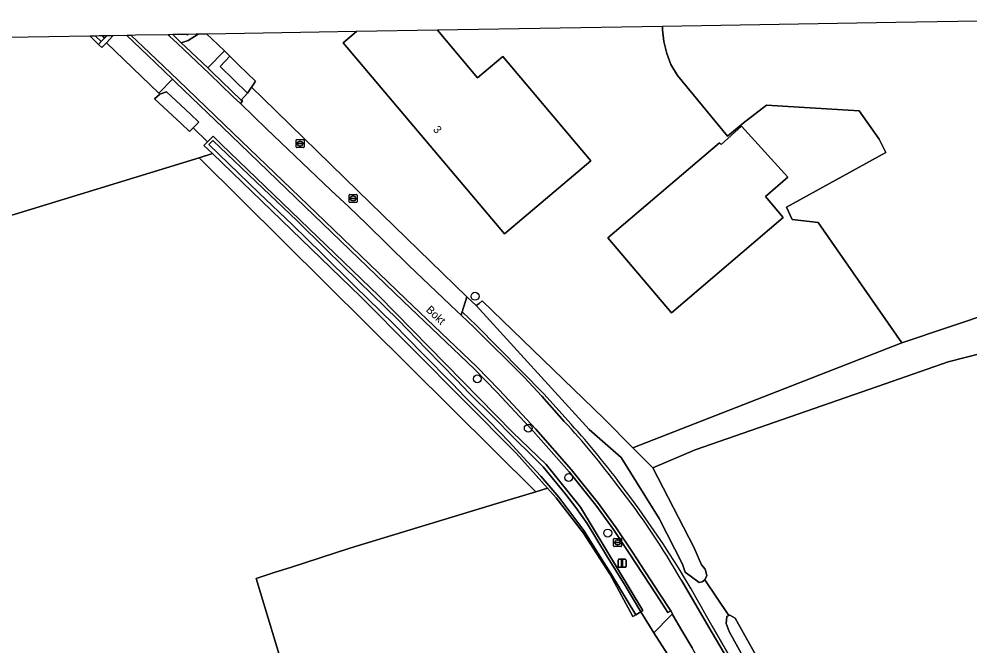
# Model space of a CAD drawing. Extents: x 162510 to 163918, y 388494 to 389774.
# Drawn here: x 163019.4 to 163138.2, y 389687.4 to 389765.6 of the extents above; entities that cross this region are included whole.
import ezdxf

# ---------------------------------------------------------------- set-up
doc = ezdxf.new("R2010")
doc.units = 0
for name, color, linetype in [('IMGEO_Afsluitpaal', 7, 'Continuous'), ('IMGEO_Berm_groen', 7, 'Continuous'), ('IMGEO_Boom', 7, 'Continuous'), ('IMGEO_Brandkraan', 7, 'Continuous'), ('IMGEO_Erf', 7, 'Continuous'), ('IMGEO_Grasland_agrarisch', 7, 'Continuous'), ('IMGEO_Grasland_overig', 7, 'Continuous'), ('IMGEO_Hek', 7, 'Continuous'), ('IMGEO_Inrit_halfverhard', 7, 'Continuous'), ('IMGEO_Kolk', 7, 'Continuous'), ('IMGEO_Loofbos', 7, 'Continuous'), ('IMGEO_Oever', 7, 'Continuous'), ('IMGEO_Openbare_ruimte_label', 7, 'Continuous'), ('IMGEO_Pand', 7, 'Continuous'), ('IMGEO_Pand_nummerreeks', 7, 'Continuous'), ('IMGEO_Rijbaan_lokaal_gesloten', 7, 'Continuous'), ('IMGEO_Rijbaan_lokaal_halfverhard', 7, 'Continuous'), ('IMGEO_Rijbaan_lokaal_open', 7, 'Continuous'), ('IMGEO_Rioolput', 7, 'Continuous'), ('IMGEO_Sloot', 7, 'Continuous'), ('IMGEO_Voetpad_open', 7, 'Continuous'), ('IMGEO_Waterloop', 7, 'Continuous')]:
    doc.layers.add(name, color=color, linetype=linetype)

msp = doc.modelspace()

# ---------------------------------------------------------------- linework, layer by layer
at = {"layer": 'IMGEO_Afsluitpaal'}
for p, q in [((163094.27, 389697.27), (163094.27, 389698.07)), ((163094.27, 389698.07), (163094.27, 389697.27)), ((163094.37, 389698.17), (163095.16, 389698.17)), ((163095.16, 389698.17), (163094.37, 389698.17)), ((163095.26, 389698.07), (163095.26, 389697.27)), ((163095.26, 389697.27), (163095.26, 389698.07)), ((163095.16, 389697.17), (163094.37, 389697.17)), ((163094.37, 389697.17), (163095.16, 389697.17))]:
    msp.add_line(p, q, dxfattribs=at)
msp.add_lwpolyline([(163094.69, 389698.04), (163094.84, 389698.04), (163094.84, 389697.29), (163094.69, 389697.29), (163094.69, 389698.04)], dxfattribs=at)
for centre, start, end in [((163094.37, 389698.07), 90, 180), ((163094.37, 389698.07), 90, 180), ((163095.16, 389698.07), 0, 90), ((163095.16, 389698.07), 360, 90), ((163094.37, 389697.27), 180, 270), ((163094.37, 389697.27), 180, 270), ((163095.16, 389697.27), 270, 0), ((163095.16, 389697.27), 270, 0)]:
    msp.add_arc(centre, 0.1, start, end, dxfattribs=at)
at = {"layer": 'IMGEO_Berm_groen'}
msp.add_lwpolyline([(163031.18, 389763.52), (163030.89, 389763.52), (163030.41, 389763.51), (163030.14, 389763.23), (163029.72, 389762.79), (163029.38, 389762.44), (163029.78, 389762.04), (163030.36, 389762.63), (163031.18, 389763.52)], dxfattribs=at)
for points in [[(163040.4, 389763.68), (163038.68, 389763.65), (163038.65, 389763.65), (163039.7, 389762.65), (163040.57, 389762.92), (163041.83, 389763.7), (163041.55, 389763.7), (163040.59, 389763.68), (163040.5, 389763.58)], [(163044.55, 389759.66), (163045.78, 389760.95), (163045.09, 389761.62), (163043.02, 389759.5), (163043.52, 389759.03), (163047.21, 389755.48), (163047.98, 389756.33)]]:
    msp.add_lwpolyline(points, close=True, dxfattribs=at)
at = {"layer": 'IMGEO_Boom'}
for centre in [(163076.41, 389731), (163076.69, 389720.69), (163083.05, 389714.53), (163088.09, 389708.37), (163092.98, 389701.44)]:
    msp.add_circle(centre, 0.489, dxfattribs=at)
at = {"layer": 'IMGEO_Brandkraan'}
for p, q in [((163093.71, 389699.84), (163093.71, 389700.7)), ((163093.78, 389700.77), (163094.64, 389700.77)), ((163093.97, 389700.26), (163093.97, 389700.28)), ((163094.01, 389700.31), (163094.41, 389700.31)), ((163094.41, 389700.23), (163094.01, 389700.23)), ((163094.2, 389700.55), (163094.22, 389700.55)), ((163094.45, 389700.28), (163094.45, 389700.26)), ((163094.71, 389700.7), (163094.71, 389699.84)), ((163094.64, 389699.77), (163093.78, 389699.77)), ((163094.22, 389699.99), (163094.2, 389699.99))]:
    msp.add_line(p, q, dxfattribs=at)
for points in [[(163093.71, 389699.84), (163093.71, 389700.7)], [(163093.78, 389700.77), (163094.64, 389700.77)], [(163094.71, 389700.7), (163094.71, 389699.84)], [(163094.64, 389699.77), (163093.78, 389699.77)]]:
    msp.add_lwpolyline(points, dxfattribs=at)
for centre, radius, start, end in [((163093.79, 389700.69), 0.0765, 91.552, 178.448), ((163093.79, 389700.69), 0.0765, 91.552, 178.448), ((163094.01, 389700.27), 0.0403, 85.8775, 175.7526), ((163094.01, 389700.26), 0.0366, 178.938, 274.7102), ((163094.41, 389700.27), 0.0386, 1.7309, 96.639), ((163094.41, 389700.27), 0.043, 264.8664, 352.4533), ((163094.63, 389700.69), 0.0765, 1.552, 88.448), ((163094.63, 389700.69), 0.0765, 1.552, 88.448), ((163093.79, 389699.84), 0.0765, 181.552, 268.448), ((163093.79, 389699.84), 0.0765, 181.552, 268.448), ((163094.63, 389699.84), 0.0765, 271.552, 358.448), ((163094.63, 389699.84), 0.0765, 271.552, 358.448)]:
    msp.add_arc(centre, radius, start, end, dxfattribs=at)
for centre, major_axis, ratio, start_param, end_param in [((163094.2, 389700.27), (-0.387, 0.002), 0.722429, 4.712389, 7.853982), ((163094.22, 389700.27), (-0.39, 0.002), 0.717154, 1.570796, 4.712389)]:
    msp.add_ellipse(centre, major_axis=major_axis, ratio=ratio, start_param=start_param, end_param=end_param, dxfattribs=at)
at = {"layer": 'IMGEO_Erf'}
for points in [[(163061.6, 389764.03), (163042.93, 389763.72), (163042.91, 389763.72), (163043.53, 389763.13), (163045.09, 389761.62), (163045.78, 389760.95), (163046.92, 389759.84), (163048.98, 389757.85), (163048.59, 389757.26), (163048.47, 389757.09), (163049.91, 389755.71), (163061.77, 389744.16), (163075.36, 389730.92), (163076.55, 389729.85), (163076.91, 389730.11), (163077.31, 389730.41), (163092.48, 389715.73), (163096.12, 389712.1), (163129.7, 389725.19), (163119.24, 389740.19), (163116.01, 389740.57), (163115.29, 389742.12), (163127.73, 389748.96), (163126.86, 389750.62), (163124.39, 389754.15), (163112.8, 389754.86), (163109.9, 389752.61), (163107.92, 389750.97), (163101.7, 389758.54), (163100.86, 389759.93), (163100.34, 389761.29), (163099.99, 389762.8), (163099.8, 389764.24), (163099.82, 389764.68), (163071.7, 389764.2), (163076.73, 389758.25), (163079.88, 389760.91), (163090.88, 389747.9), (163080.1, 389738.79), (163059.94, 389762.63)], [(163106.94, 389750.15), (163107.14, 389749.92), (163109.68, 389752.23), (163115.47, 389745.85), (163112.67, 389743.44), (163114.9, 389740.84), (163100.93, 389728.94), (163093, 389738.3)]]:
    msp.add_lwpolyline(points, close=True, dxfattribs=at)
for points in [[(163000, 389735.45), (163041.93, 389748.28), (163043.62, 389748.8), (163042.54, 389749.83), (163042.99, 389750.29), (163041.21, 389752.03), (163040.72, 389751.57), (163039.7, 389752.55), (163036.36, 389755.62), (163036.97, 389756.17), (163037.03, 389756.22), (163036.89, 389756.36), (163030.36, 389762.63), (163029.78, 389762.04), (163029.38, 389762.44), (163028.34, 389763.47), (163028.29, 389763.47), (163000, 389763)], [(163101.17, 389685.17), (163098.73, 389688.98), (163097.11, 389691.63), (163096.48, 389691.25), (163096.13, 389691.04), (163093.29, 389696.28), (163089.93, 389701.45), (163086.53, 389705.83), (163085.44, 389707.04), (163083.99, 389706.6), (163079.14, 389705.13), (163060.78, 389699.57), (163053.35, 389697.16), (163051.31, 389696.5), (163050.19, 389696.14), (163049.05, 389695.77), (163063.36, 389648.6)]]:
    msp.add_lwpolyline(points, dxfattribs=at)
at = {"layer": 'IMGEO_Grasland_agrarisch'}
msp.add_lwpolyline([(163130.74, 389593.91), (163130.82, 389595.75), (163129.49, 389604.01), (163127.31, 389615.89), (163124.17, 389630.54), (163122.35, 389637.11), (163120.08, 389643.72), (163118.81, 389646.87), (163066.29, 389636.03), (163063.36, 389648.6), (163049.05, 389695.77), (163050.19, 389696.14), (163051.31, 389696.5), (163053.35, 389697.16), (163060.78, 389699.57), (163079.14, 389705.13), (163083.99, 389706.6), (163041.93, 389748.28), (163000, 389735.45)], dxfattribs=at)
at = {"layer": 'IMGEO_Grasland_overig'}
for points in [[(163154.74, 389765.6), (163128.98, 389765.17), (163099.82, 389764.68), (163099.8, 389764.24), (163099.99, 389762.8), (163100.34, 389761.29), (163100.86, 389759.93), (163101.7, 389758.54), (163107.92, 389750.97), (163109.9, 389752.61), (163112.8, 389754.86), (163124.39, 389754.15), (163126.86, 389750.62), (163127.73, 389748.96), (163115.29, 389742.12), (163116.01, 389740.57), (163119.24, 389740.19), (163129.7, 389725.19), (163141.35, 389729.09), (163168.42, 389737.11), (163201.99, 389747.04)], [(163095.83, 389708.99), (163094.66, 389710.87), (163090.67, 389714.38), (163076.55, 389729.85), (163075.36, 389730.92), (163074.78, 389729.06), (163076.53, 389727.41), (163085.04, 389718.79), (163087.98, 389715.5)], [(163113.58, 389679.31), (163108.13, 389689.14), (163107.76, 389690.16), (163107.87, 389691.02), (163108.1, 389691.14), (163105.09, 389695.61), (163104.76, 389695.34), (163104.38, 389695.26), (163102.66, 389696.57), (163102.32, 389697.57), (163099.41, 389703.24), (163095.83, 389708.99)], [(163105.96, 389689.9), (163109.12, 389684.51), (163111.32, 389680.67), (163113.47, 389676.83), (163115.49, 389672.95), (163116.92, 389670.18), (163121.49, 389660.72)]]:
    msp.add_lwpolyline(points, dxfattribs=at)
for points in [[(163038.6, 389758.11), (163036.89, 389756.36), (163037.03, 389756.22), (163037.87, 389756.52), (163040.87, 389753.73), (163041.92, 389752.71), (163041.21, 389752.03), (163042.99, 389750.29), (163043.68, 389750.98), (163044.68, 389750), (163064.38, 389731.06), (163081.07, 389714.04), (163085.27, 389709.98), (163089.56, 389704.66), (163097.34, 389691.77), (163097.11, 389691.63), (163098.73, 389688.98), (163100.83, 389691.13), (163101.05, 389691.35), (163100.84, 389691.74), (163100.5, 389691.52), (163099.05, 389693.74), (163095.64, 389698.95), (163093.69, 389701.88), (163091.51, 389704.92), (163088.14, 389709.08), (163083.7, 389714.12), (163079.11, 389719.02), (163076.34, 389721.88), (163067.43, 389730.4), (163056.26, 389741.13), (163045.93, 389751.08), (163039.04, 389757.69)], [(163062.1, 389730.98), (163043.62, 389748.8), (163041.93, 389748.28), (163083.99, 389706.6), (163085.44, 389707.04), (163081.53, 389711.41)]]:
    msp.add_lwpolyline(points, close=True, dxfattribs=at)
for centre, radius, start, end in [((163016.59, 389649.58), 97.17, 36.6639, 42.7185), ((162991.94, 389628.88), 129.32, 28.1533, 37.4998)]:
    msp.add_arc(centre, radius, start, end, dxfattribs=at)
at = {"layer": 'IMGEO_Hek'}
for points in [[(162950.22, 389720.21), (163000, 389735.45), (163041.93, 389748.28), (163043.62, 389748.8)], [(163050.19, 389696.14), (163051.31, 389696.5), (163053.35, 389697.16), (163060.78, 389699.57), (163079.14, 389705.13), (163083.99, 389706.6), (163085.44, 389707.04)]]:
    msp.add_lwpolyline(points, dxfattribs=at)
at = {"layer": 'IMGEO_Inrit_halfverhard'}
msp.add_lwpolyline([(163041.83, 389763.7), (163040.57, 389762.92), (163039.7, 389762.65), (163040.3, 389762.09), (163043.02, 389759.5), (163045.09, 389761.62), (163043.53, 389763.13), (163042.91, 389763.72)], close=True, dxfattribs=at)
at = {"layer": 'IMGEO_Kolk'}
for p, q in [((163054.05, 389749.63), (163054.05, 389750.48)), ((163054.12, 389750.55), (163054.97, 389750.55)), ((163054.3, 389750.05), (163054.3, 389750.06)), ((163054.35, 389750.1), (163054.75, 389750.1)), ((163054.53, 389750.33), (163054.56, 389750.33)), ((163054.79, 389750.06), (163054.79, 389750.05)), ((163055.05, 389750.48), (163055.05, 389749.63)), ((163054.97, 389749.55), (163054.12, 389749.55)), ((163054.74, 389750.01), (163054.34, 389750.01)), ((163054.56, 389749.77), (163054.53, 389749.77))]:
    msp.add_line(p, q, dxfattribs=at)
for points in [[(163054.05, 389749.63), (163054.05, 389750.48)], [(163054.12, 389750.55), (163054.97, 389750.55)], [(163055.05, 389750.48), (163055.05, 389749.63)], [(163054.97, 389749.55), (163054.12, 389749.55)]]:
    msp.add_lwpolyline(points, dxfattribs=at)
for centre, radius, start, end in [((163054.12, 389750.48), 0.0765, 91.552, 178.448), ((163054.12, 389750.48), 0.0765, 91.552, 178.448), ((163054.35, 389750.06), 0.0403, 85.8775, 175.7526), ((163054.34, 389750.05), 0.0366, 178.938, 274.7102), ((163054.75, 389750.05), 0.043, 264.8664, 352.4533), ((163054.75, 389750.06), 0.0386, 1.7309, 96.639), ((163054.97, 389750.48), 0.0765, 1.552, 88.448), ((163054.97, 389750.48), 0.0765, 1.552, 88.448), ((163054.12, 389749.63), 0.0765, 181.552, 268.448), ((163054.12, 389749.63), 0.0765, 181.552, 268.448), ((163054.97, 389749.63), 0.0765, 271.552, 358.448), ((163054.97, 389749.63), 0.0765, 271.552, 358.448)]:
    msp.add_arc(centre, radius, start, end, dxfattribs=at)
for centre, major_axis, ratio, start_param, end_param in [((163054.53, 389750.05), (-0.387, 0.002), 0.722429, 4.712389, 7.853982), ((163054.56, 389750.05), (-0.39, 0.002), 0.717154, 1.570796, 4.712389)]:
    msp.add_ellipse(centre, major_axis=major_axis, ratio=ratio, start_param=start_param, end_param=end_param, dxfattribs=at)
at = {"layer": 'IMGEO_Loofbos'}
msp.add_lwpolyline([(163146.11, 389725.52), (163135.48, 389722.83), (163127.61, 389720.05), (163103.91, 389711.81), (163098.61, 389709.59), (163103.73, 389699.69), (163104.68, 389697.49), (163105.15, 389696.93), (163105.37, 389696.14), (163105.09, 389695.61), (163108.1, 389691.14), (163108.23, 389691.19), (163108.91, 389690.83), (163115.83, 389678.38), (163116.72, 389677.86), (163117.45, 389677.93), (163121.25, 389679.04), (163131.11, 389682.28), (163161.64, 389691.33)], dxfattribs=at)
at = {"layer": 'IMGEO_Oever'}
for points in [[(163029, 389763.48), (163028.34, 389763.47), (163029.38, 389762.44), (163029.72, 389762.79)], [(163030.41, 389763.51), (163029.88, 389763.5), (163030.14, 389763.23)], [(163043.15, 389749.92), (163043.67, 389750.46), (163049.92, 389744.43), (163054.13, 389740.45), (163057.78, 389736.87), (163061.87, 389732.84), (163066.8, 389728.05), (163070.34, 389724.4), (163074.1, 389720.57), (163075.64, 389718.96), (163078.77, 389715.85), (163081.19, 389713.38), (163083.59, 389711.03), (163084.93, 389709.69), (163087.73, 389706.24), (163088.99, 389704.63), (163090.4, 389702.64), (163092.83, 389698.63), (163095.14, 389694.9), (163097.11, 389691.63), (163097.34, 389691.77), (163089.56, 389704.66), (163085.27, 389709.98), (163081.07, 389714.04), (163064.38, 389731.06), (163044.68, 389750), (163043.68, 389750.98), (163042.99, 389750.29), (163042.54, 389749.83), (163043.62, 389748.8), (163062.1, 389730.98), (163081.53, 389711.41), (163085.44, 389707.04), (163086.53, 389705.83), (163089.93, 389701.45), (163093.29, 389696.28), (163096.13, 389691.04), (163096.48, 389691.25), (163093.38, 389696.4), (163092.19, 389698.24), (163090, 389701.76), (163088.26, 389704.08), (163086.86, 389705.93), (163084.64, 389708.56), (163082.93, 389710.39), (163080.66, 389712.85), (163078.24, 389715.33), (163075.11, 389718.44), (163073.57, 389720.05), (163069.81, 389723.88), (163066.28, 389727.53), (163061.35, 389732.31), (163057.26, 389736.34), (163053.62, 389739.92), (163049.41, 389743.89)]]:
    msp.add_lwpolyline(points, close=True, dxfattribs=at)
at = {"layer": 'IMGEO_Pand'}
for points in [[(163061.6, 389764.03), (163059.94, 389762.63), (163080.1, 389738.79), (163090.88, 389747.9), (163079.88, 389760.91), (163076.73, 389758.25), (163071.7, 389764.2)], [(163114.9, 389740.84), (163112.67, 389743.44), (163115.47, 389745.85), (163109.68, 389752.23), (163107.14, 389749.92), (163106.94, 389750.15), (163093, 389738.3), (163100.93, 389728.94)]]:
    msp.add_lwpolyline(points, close=True, dxfattribs=at)
at = {"layer": 'IMGEO_Rijbaan_lokaal_gesloten'}
for points in [[(163087.55, 389715.37), (163084.74, 389718.53), (163082.54, 389720.88), (163076.25, 389727.13), (163074.65, 389728.64), (163074.12, 389729.14), (163068.12, 389734.84), (163062.86, 389740.02), (163060.62, 389742.15), (163058.38, 389744.23), (163050.35, 389751.88), (163047.09, 389755.05), (163046.17, 389755.93), (163043.25, 389758.74), (163040.02, 389761.8), (163039.24, 389762.55), (163038.25, 389763.47), (163038.07, 389763.64), (163034.01, 389763.57), (163033.47, 389763.56)], [(163033.47, 389763.56), (163035.76, 389761.38), (163039.32, 389757.98), (163046.2, 389751.36), (163056.54, 389741.42), (163067.71, 389730.69), (163076.61, 389722.17), (163079.4, 389719.3), (163083.99, 389714.39), (163088.44, 389709.34), (163091.83, 389705.15), (163094.02, 389702.1), (163095.98, 389699.17), (163099.39, 389693.96), (163100.84, 389691.74), (163101.05, 389691.35), (163101.12, 389691.21), (163102.25, 389689.27), (163103.52, 389687.12)], [(163121.13, 389660.55), (163119.32, 389664.34), (163116.56, 389670), (163115.13, 389672.76), (163113.12, 389676.63), (163110.97, 389680.47), (163108.78, 389684.31), (163105.61, 389689.69), (163102.22, 389695.47)]]:
    msp.add_lwpolyline(points, dxfattribs=at)
for centre, radius, start, end in [((163016.69, 389649.66), 96.64, 36.6551, 42.8406), ((163016.2, 389646.21), 99.13, 29.7944, 38.0848)]:
    msp.add_arc(centre, radius, start, end, dxfattribs=at)
at = {"layer": 'IMGEO_Rijbaan_lokaal_halfverhard'}
for points in [[(163033.47, 389763.56), (163032.99, 389763.55), (163032.9, 389763.55), (163035.48, 389761.09), (163038.6, 389758.11), (163039.04, 389757.69), (163045.93, 389751.08), (163056.26, 389741.13), (163067.43, 389730.4), (163076.34, 389721.88), (163079.11, 389719.02), (163083.7, 389714.12), (163088.14, 389709.08), (163091.51, 389704.92), (163093.69, 389701.88), (163095.64, 389698.95), (163099.05, 389693.74), (163100.5, 389691.52), (163100.84, 389691.74), (163099.39, 389693.96), (163095.98, 389699.17), (163094.02, 389702.1), (163091.83, 389705.15), (163088.44, 389709.34), (163083.99, 389714.39), (163079.4, 389719.3), (163076.61, 389722.17), (163067.71, 389730.69), (163056.54, 389741.42), (163046.2, 389751.36), (163039.32, 389757.98), (163035.76, 389761.38)], [(163038.07, 389763.64), (163038.25, 389763.47), (163039.24, 389762.55), (163040.02, 389761.8), (163043.25, 389758.74), (163046.17, 389755.93), (163047.09, 389755.05), (163047.36, 389755.34), (163047.21, 389755.48), (163043.52, 389759.03), (163043.02, 389759.5), (163040.3, 389762.09), (163039.7, 389762.65), (163038.65, 389763.65), (163038.3, 389763.64)]]:
    msp.add_lwpolyline(points, close=True, dxfattribs=at)
for points in [[(163074.78, 389729.06), (163074.65, 389728.64), (163076.25, 389727.13), (163082.54, 389720.88), (163084.74, 389718.53), (163087.55, 389715.37)], [(163087.98, 389715.5), (163085.04, 389718.79), (163076.53, 389727.41), (163074.78, 389729.06)], [(163102.22, 389695.47), (163105.61, 389689.69), (163108.78, 389684.31), (163110.97, 389680.47), (163113.12, 389676.63), (163115.13, 389672.76), (163116.56, 389670), (163119.32, 389664.34), (163121.13, 389660.55)], [(163121.49, 389660.72), (163116.92, 389670.18), (163115.49, 389672.95), (163113.47, 389676.83), (163111.32, 389680.67), (163109.12, 389684.51), (163105.96, 389689.9)]]:
    msp.add_lwpolyline(points, dxfattribs=at)
for centre, radius, start, end in [((163016.69, 389649.66), 96.64, 36.6551, 42.8406), ((163016.59, 389649.58), 97.17, 36.6639, 42.7185), ((163016.2, 389646.21), 99.13, 29.7944, 38.0848), ((162991.94, 389628.88), 129.32, 28.1533, 37.4998)]:
    msp.add_arc(centre, radius, start, end, dxfattribs=at)
at = {"layer": 'IMGEO_Rijbaan_lokaal_open'}
for points in [[(163032.9, 389763.55), (163031.18, 389763.52), (163030.36, 389762.63), (163036.89, 389756.36), (163038.6, 389758.11), (163035.48, 389761.09)], [(163101.05, 389691.35), (163100.83, 389691.13), (163098.73, 389688.98), (163101.17, 389685.17), (163101.39, 389685.23), (163103.88, 389685.65), (163104.31, 389685.72), (163104.28, 389685.76), (163103.52, 389687.12), (163102.25, 389689.27), (163101.12, 389691.21)]]:
    msp.add_lwpolyline(points, close=True, dxfattribs=at)
at = {"layer": 'IMGEO_Rioolput'}
for p, q in [((163060.66, 389742.78), (163060.66, 389743.63)), ((163060.74, 389743.71), (163061.59, 389743.71)), ((163060.92, 389743.2), (163060.92, 389743.21)), ((163061.36, 389743.16), (163060.96, 389743.16)), ((163060.97, 389743.25), (163061.36, 389743.25)), ((163061.15, 389743.49), (163061.18, 389743.49)), ((163061.17, 389742.93), (163061.15, 389742.93)), ((163061.41, 389743.21), (163061.41, 389743.2)), ((163061.67, 389743.63), (163061.67, 389742.78)), ((163061.59, 389742.71), (163060.74, 389742.71))]:
    msp.add_line(p, q, dxfattribs=at)
for points in [[(163060.66, 389742.78), (163060.66, 389743.63)], [(163060.74, 389743.71), (163061.59, 389743.71)], [(163061.67, 389743.63), (163061.67, 389742.78)], [(163061.59, 389742.71), (163060.74, 389742.71)]]:
    msp.add_lwpolyline(points, dxfattribs=at)
for centre, radius, start, end in [((163060.74, 389743.63), 0.0765, 91.552, 178.448), ((163060.74, 389743.63), 0.0765, 91.552, 178.448), ((163060.96, 389743.21), 0.0403, 85.8775, 175.7526), ((163060.96, 389743.2), 0.0366, 178.938, 274.7102), ((163061.37, 389743.21), 0.0386, 1.7309, 96.639), ((163061.36, 389743.21), 0.043, 264.8664, 352.4533), ((163061.59, 389743.63), 0.0765, 1.552, 88.448), ((163061.59, 389743.63), 0.0765, 1.552, 88.448), ((163060.74, 389742.78), 0.0765, 181.552, 268.448), ((163060.74, 389742.78), 0.0765, 181.552, 268.448), ((163061.59, 389742.78), 0.0765, 271.552, 358.448), ((163061.59, 389742.78), 0.0765, 271.552, 358.448)]:
    msp.add_arc(centre, radius, start, end, dxfattribs=at)
for centre, major_axis, ratio, start_param, end_param in [((163061.15, 389743.21), (-0.387, 0.002), 0.722429, 4.712389, 7.853982), ((163061.18, 389743.21), (-0.39, 0.002), 0.717154, 1.570796, 4.712389)]:
    msp.add_ellipse(centre, major_axis=major_axis, ratio=ratio, start_param=start_param, end_param=end_param, dxfattribs=at)
at = {"layer": 'IMGEO_Sloot'}
for points in [[(163029.88, 389763.5), (163029.46, 389763.49), (163029, 389763.48), (163029.72, 389762.79), (163030.14, 389763.23)], [(163040.59, 389763.68), (163040.43, 389763.68), (163040.4, 389763.68), (163040.5, 389763.58)], [(163046.92, 389759.84), (163045.78, 389760.95), (163044.55, 389759.66), (163047.98, 389756.33), (163048.47, 389757.09), (163048.59, 389757.26), (163048.98, 389757.85)], [(163037.03, 389756.22), (163036.97, 389756.17), (163036.36, 389755.62), (163039.7, 389752.55), (163040.72, 389751.57), (163041.21, 389752.03), (163041.92, 389752.71), (163040.87, 389753.73), (163037.87, 389756.52)]]:
    msp.add_lwpolyline(points, close=True, dxfattribs=at)
for points in [[(163201.99, 389747.04), (163168.42, 389737.11), (163141.35, 389729.09), (163129.7, 389725.19), (163096.12, 389712.1), (163098.61, 389709.59), (163103.91, 389711.81), (163127.61, 389720.05), (163135.48, 389722.83), (163146.11, 389725.52), (163158.42, 389728.94), (163175.95, 389733.92), (163192.61, 389739.52), (163206.42, 389743.82)], [(163161.64, 389691.33), (163131.11, 389682.28), (163121.25, 389679.04), (163117.45, 389677.93), (163116.72, 389677.86), (163115.83, 389678.38), (163108.91, 389690.83), (163108.23, 389691.19), (163108.1, 389691.14), (163107.87, 389691.02), (163107.76, 389690.16), (163108.13, 389689.14), (163113.58, 389679.31), (163122.8, 389662.04), (163123.23, 389661.71), (163123.61, 389661.72), (163124.04, 389662.03), (163123.95, 389662.66), (163122.28, 389667.1), (163118.6, 389675.44), (163119.39, 389675.84), (163128.29, 389678.66), (163138.31, 389681.76)]]:
    msp.add_lwpolyline(points, dxfattribs=at)
at = {"layer": 'IMGEO_Voetpad_open'}
msp.add_lwpolyline([(163061.77, 389744.16), (163049.91, 389755.71), (163048.47, 389757.09), (163047.98, 389756.33), (163047.21, 389755.48), (163047.36, 389755.34), (163047.09, 389755.05), (163050.35, 389751.88), (163058.38, 389744.23), (163060.62, 389742.15), (163062.86, 389740.02), (163068.12, 389734.84), (163074.12, 389729.14), (163074.65, 389728.64), (163074.78, 389729.06), (163075.36, 389730.92)], close=True, dxfattribs=at)
at = {"layer": 'IMGEO_Waterloop'}
for points in [[(163043.67, 389750.46), (163043.15, 389749.92), (163049.41, 389743.89), (163053.62, 389739.92), (163057.26, 389736.34), (163061.35, 389732.31), (163066.28, 389727.53), (163069.81, 389723.88), (163073.57, 389720.05), (163075.11, 389718.44), (163078.24, 389715.33), (163080.66, 389712.85), (163082.93, 389710.39), (163084.64, 389708.56), (163086.86, 389705.93), (163088.26, 389704.08), (163090, 389701.76), (163092.19, 389698.24), (163093.38, 389696.4), (163096.48, 389691.25), (163097.11, 389691.63), (163095.14, 389694.9), (163092.83, 389698.63), (163090.4, 389702.64), (163088.99, 389704.63), (163087.73, 389706.24), (163084.93, 389709.69), (163083.59, 389711.03), (163081.19, 389713.38), (163078.77, 389715.85), (163075.64, 389718.96), (163074.1, 389720.57), (163070.34, 389724.4), (163066.8, 389728.05), (163061.87, 389732.84), (163057.78, 389736.87), (163054.13, 389740.45), (163049.92, 389744.43)], [(163077.31, 389730.41), (163076.91, 389730.11), (163076.55, 389729.85), (163090.67, 389714.38), (163094.66, 389710.87), (163095.83, 389708.99), (163099.41, 389703.24), (163102.32, 389697.57), (163102.66, 389696.57), (163104.38, 389695.26), (163104.76, 389695.34), (163105.09, 389695.61), (163105.37, 389696.14), (163105.15, 389696.93), (163104.68, 389697.49), (163103.73, 389699.69), (163098.61, 389709.59), (163096.12, 389712.1), (163092.48, 389715.73)]]:
    msp.add_lwpolyline(points, close=True, dxfattribs=at)

# ---------------------------------------------------------------- texts
at = {"layer": 'IMGEO_Openbare_ruimte_label'}
msp.add_text('Bokt', height=1, rotation=316.4584, dxfattribs=at).set_placement((163070.19, 389729.21))
at = {"layer": 'IMGEO_Pand_nummerreeks'}
msp.add_text('3', height=1, rotation=310.2157, dxfattribs=at).set_placement((163071.09, 389751.77))

doc.saveas('drawing.dxf')
